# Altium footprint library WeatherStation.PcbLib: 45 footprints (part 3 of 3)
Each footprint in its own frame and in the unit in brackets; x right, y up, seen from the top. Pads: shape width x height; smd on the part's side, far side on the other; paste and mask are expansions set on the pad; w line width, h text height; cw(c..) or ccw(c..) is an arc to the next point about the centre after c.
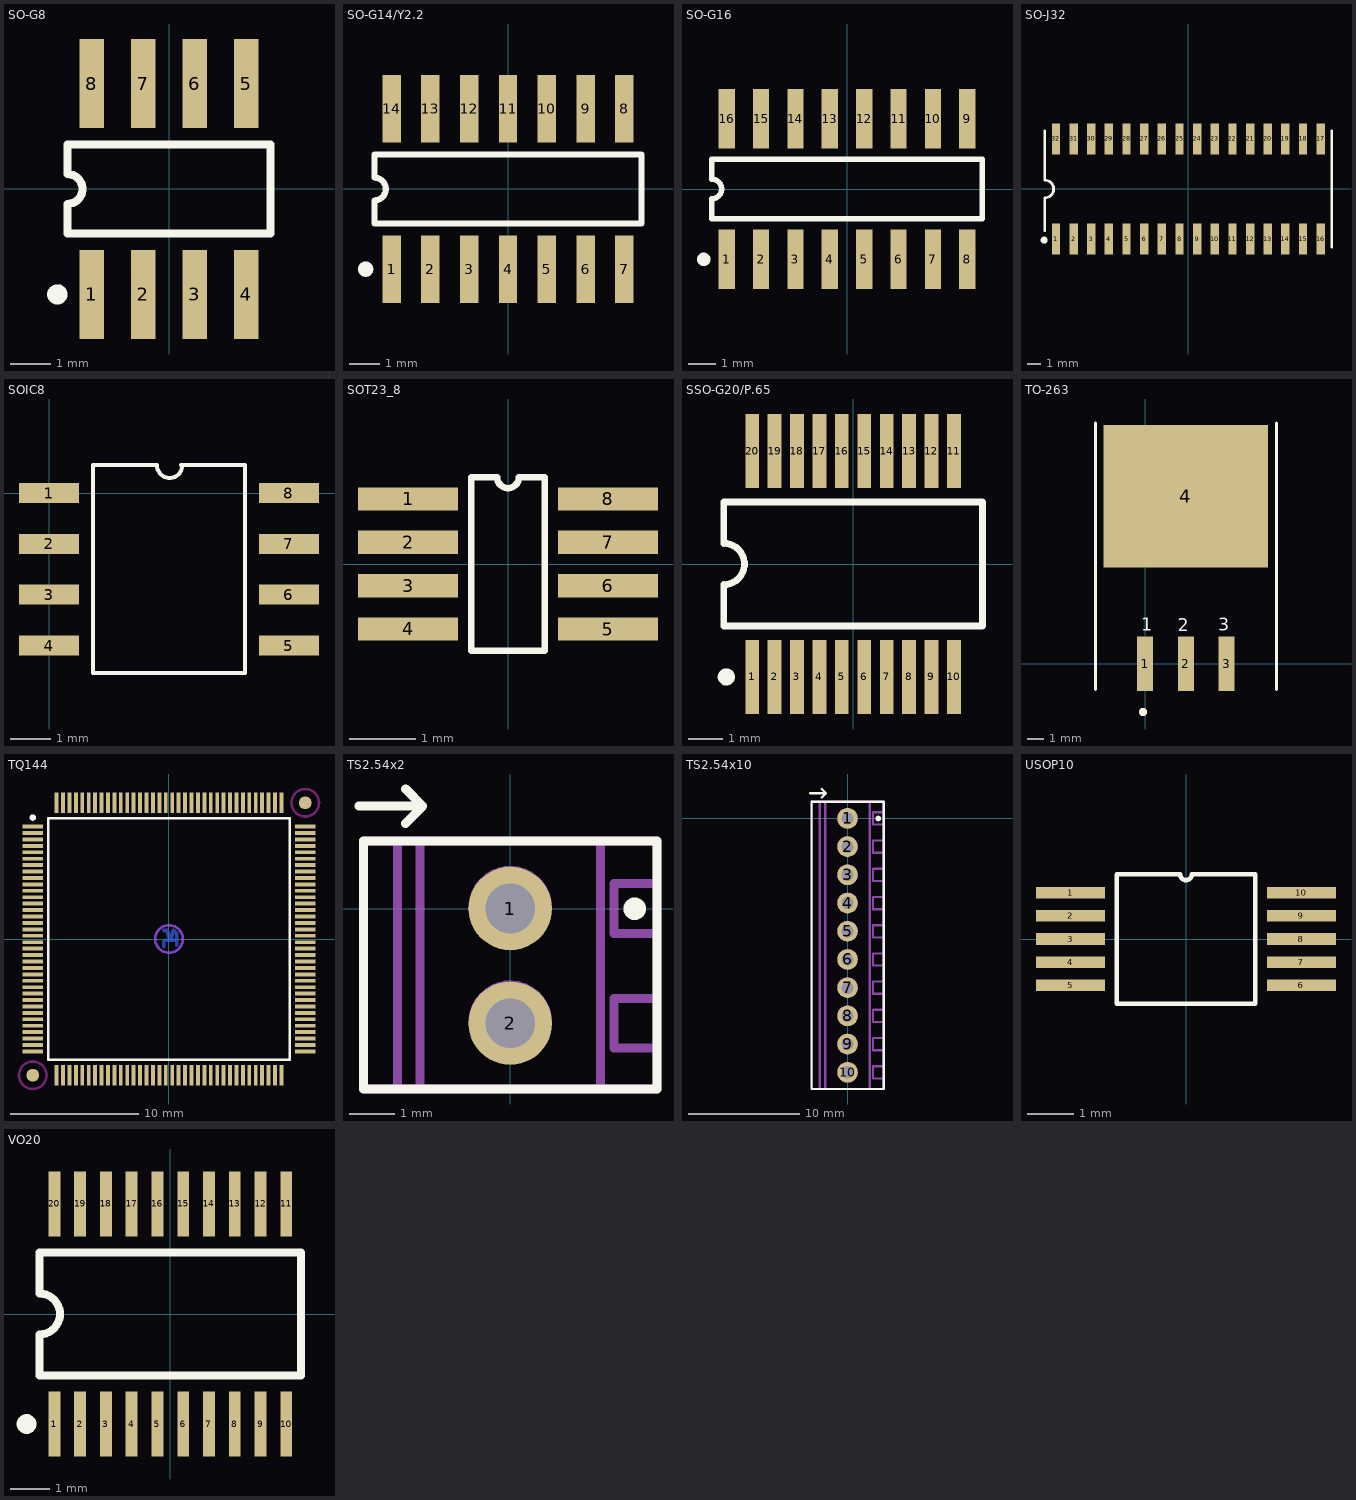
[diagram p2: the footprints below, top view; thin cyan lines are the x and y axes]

## SO-G8 [mm]
pads (8):
  rect 0.6x2.2 smd: 1(-1.905,-2.6) 2(-0.635,-2.6) 3(0.635,-2.6) 4(1.905,-2.6) 5(1.905,2.6) 6(0.635,2.6) 7(-0.635,2.6) 8(-1.905,2.6)
Top Overlay:
  circle w0.25: c-2.755,-2.6 r0.125
  lines w0.2: -2.5,-1.1 -2.5,-0.367 ccw(c-2.5,0) -2.5,0.367 -2.5,1.1 2.5,1.1 2.5,-1.1 -2.5,-1.1

## SO-G14/Y2.2 [mm]
pads (14):
  rect 0.6x2.2 smd: 1(-3.81,-2.625) 2(-2.54,-2.625) 3(-1.27,-2.625) 4(0,-2.625) 5(1.27,-2.625) 6(2.54,-2.625) 7(3.81,-2.625) 8(3.81,2.625) 9(2.54,2.625) 10(1.27,2.625) 11(0,2.625) 12(-1.27,2.625) 13(-2.54,2.625) 14(-3.81,2.625)
Top Overlay:
  circle w0.25: c-4.66,-2.625 r0.125
  lines w0.2: -4.375,-1.125 -4.375,-0.375 ccw(c-4.375,0) -4.375,0.375 -4.375,1.125 4.375,1.125 4.375,-1.125 -4.375,-1.125

## SO-G16 [mm]
pads (16):
  rect 0.6x2.2 smd: 1(-4.445,-2.6) 2(-3.175,-2.6) 3(-1.905,-2.6) 4(-0.635,-2.6) 5(0.635,-2.6) 6(1.905,-2.6) 7(3.175,-2.6) 8(4.445,-2.6) 9(4.445,2.6) 10(3.175,2.6) 11(1.905,2.6) 12(0.635,2.6) 13(-0.635,2.6) 14(-1.905,2.6) 15(-3.175,2.6) 16(-4.445,2.6)
Top Overlay:
  circle w0.25: c-5.295,-2.6 r0.125
  lines w0.2: -5,-1.1 -5,-0.367 ccw(c-5,0) -5,0.367 -5,1.1 5,1.1 5,-1.1 -5,-1.1

## SO-J32 [mm]
pads (32):
  rect 0.6x2.2 smd: 1(-9.525,-3.6) 2(-8.255,-3.6) 3(-6.985,-3.6) 4(-5.715,-3.6) 5(-4.445,-3.6) 6(-3.175,-3.6) 7(-1.905,-3.6) 8(-0.635,-3.6) 9(0.635,-3.6) 10(1.905,-3.6) 11(3.175,-3.6) 12(4.445,-3.6) 13(5.715,-3.6) 14(6.985,-3.6) 15(8.255,-3.6) 16(9.525,-3.6) 17(9.525,3.6) 18(8.255,3.6) 19(6.985,3.6) 20(5.715,3.6) 21(4.445,3.6) 22(3.175,3.6) 23(1.905,3.6) 24(0.635,3.6) 25(-0.635,3.6) 26(-1.905,3.6) 27(-3.175,3.6) 28(-4.445,3.6) 29(-5.715,3.6) 30(-6.985,3.6) 31(-8.255,3.6) 32(-9.525,3.6)
Top Overlay:
  circle w0.25: c-10.375,-3.676 r0.125
  lines w0.2: -10.325,-2.996 -10.325,-0.635 ccw(c-10.325,0) -10.325,0.635 -10.325,4.191 ; 10.325,-4.191 10.325,4.191

## SOIC8 [mm]
pads (8):
  rect 1.5x0.5 smd: 1(0,0) 2(0,-1.27) 3(0,-2.54) 4(0,-3.81) 5(6,-3.81) 6(6,-2.54) 7(6,-1.27) 8(6,0)
Top Overlay:
  lines w0.1: 3.3,0.7 4.9,0.7 4.9,-4.5 1.1,-4.5 1.1,0.7 2.7,0.7 ccw(c3.017,0.7) 3.335,0.7

## SOT23_8 [mm]
pads (8):
  rect 1.5x0.35 smd: 1(-1.5,0.975) 2(-1.5,0.325) 3(-1.5,-0.325) 4(-1.5,-0.975) 5(1.5,-0.975) 6(1.5,-0.325) 7(1.5,0.325) 8(1.5,0.975)
Top Overlay:
  lines w0.1: -0.553,-1.3 0.553,-1.3 0.553,1.3 0.162,1.3 cw(c0,1.3) -0.162,1.3 -0.553,1.3 -0.553,-1.3

## SSO-G20/P.65 [mm]
pads (20):
  rect 0.4x2.15 smd: 1(-2.925,-3.275) 2(-2.275,-3.275) 3(-1.625,-3.275) 4(-0.975,-3.275) 5(-0.325,-3.275) 6(0.325,-3.275) 7(0.975,-3.275) 8(1.625,-3.275) 9(2.275,-3.275) 10(2.925,-3.275) 11(2.925,3.275) 12(2.275,3.275) 13(1.625,3.275) 14(0.975,3.275) 15(0.325,3.275) 16(-0.325,3.275) 17(-0.975,3.275) 18(-1.625,3.275) 19(-2.275,3.275) 20(-2.925,3.275)
Top Overlay:
  circle w0.25: c-3.675,-3.275 r0.125
  lines w0.2: -3.75,-1.8 -3.75,-0.6 ccw(c-3.75,0) -3.75,0.6 -3.75,1.8 3.75,1.8 3.75,-1.8 -3.75,-1.8

## TO-263 [mm]
pads (4):
  rect 1x3.4 smd: 1(0,0) 2(2.54,0) 3(5.08,0)
  rect 10.25x8.9 smd: 4(2.54,10.45)
Top Overlay:
  circle w0.25: c-0.125,-3 r0.125
  lines w0.2: -3.1,-1.6 -3.1,15 ; 8.2,-1.6 8.2,15
  text "1" at -0.25,2.075 h0.8
  text "3" at 4.572,2.075 h0.8
  text "2" at 2.032,2.032 h0.8

## TQ144 [mm]
pads (146):
  rect 1.6x0.3 smd: 1(-10.6,8.75) 2(-10.6,8.25) 3(-10.6,7.75) 4(-10.6,7.25) 5(-10.6,6.75) 6(-10.6,6.25) 7(-10.6,5.75) 8(-10.6,5.25) 9(-10.6,4.75) 10(-10.6,4.25) 11(-10.6,3.75) 12(-10.6,3.25) 13(-10.6,2.75) 14(-10.6,2.25) 15(-10.6,1.75) 16(-10.6,1.25) 17(-10.6,0.75) 18(-10.6,0.25) 19(-10.6,-0.25) 20(-10.6,-0.75) 21(-10.6,-1.25) 22(-10.6,-1.75) 23(-10.6,-2.25) 24(-10.6,-2.75) 25(-10.6,-3.25) 26(-10.6,-3.75) 27(-10.6,-4.25) 28(-10.6,-4.75) 29(-10.6,-5.25) 30(-10.6,-5.75) 31(-10.6,-6.25) 32(-10.6,-6.75) 33(-10.6,-7.25) 34(-10.6,-7.75) 35(-10.6,-8.25) 36(-10.6,-8.75) 73(10.6,-8.75) 74(10.6,-8.25) 75(10.6,-7.75) 76(10.6,-7.25) 77(10.6,-6.75) 78(10.6,-6.25) 79(10.6,-5.75) 80(10.6,-5.25) 81(10.6,-4.75) 82(10.6,-4.25) 83(10.6,-3.75) 84(10.6,-3.25) 85(10.6,-2.75) 86(10.6,-2.25) 87(10.6,-1.75) 88(10.6,-1.25) 89(10.6,-0.75) 90(10.6,-0.25) 91(10.6,0.25) 92(10.6,0.75) 93(10.6,1.25) 94(10.6,1.75) 95(10.6,2.25) 96(10.6,2.75) 97(10.6,3.25) 98(10.6,3.75) 99(10.6,4.25) 100(10.6,4.75) 101(10.6,5.25) 102(10.6,5.75) 103(10.6,6.25) 104(10.6,6.75) 105(10.6,7.25) 106(10.6,7.75) 107(10.6,8.25) 108(10.6,8.75)
  rect 0.3x1.6 smd: 37(-8.75,-10.6) 38(-8.25,-10.6) 39(-7.75,-10.6) 40(-7.25,-10.6) 41(-6.75,-10.6) 42(-6.25,-10.6) 43(-5.75,-10.6) 44(-5.25,-10.6) 45(-4.75,-10.6) 46(-4.25,-10.6) 47(-3.75,-10.6) 48(-3.25,-10.6) 49(-2.75,-10.6) 50(-2.25,-10.6) 51(-1.75,-10.6) 52(-1.25,-10.6) 53(-0.75,-10.6) 54(-0.25,-10.6) 55(0.25,-10.6) 56(0.75,-10.6) 57(1.25,-10.6) 58(1.75,-10.6) 59(2.25,-10.6) 60(2.75,-10.6) 61(3.25,-10.6) 62(3.75,-10.6) 63(4.25,-10.6) 64(4.75,-10.6) 65(5.25,-10.6) 66(5.75,-10.6) 67(6.25,-10.6) 68(6.75,-10.6) 69(7.25,-10.6) 70(7.75,-10.6) 71(8.25,-10.6) 72(8.75,-10.6) 109(8.75,10.6) 110(8.25,10.6) 111(7.75,10.6) 112(7.25,10.6) 113(6.75,10.6) 114(6.25,10.6) 115(5.75,10.6) 116(5.25,10.6) 117(4.75,10.6) 118(4.25,10.6) 119(3.75,10.6) 120(3.25,10.6) 121(2.75,10.6) 122(2.25,10.6) 123(1.75,10.6) 124(1.25,10.6) 125(0.75,10.6) 126(0.25,10.6) 127(-0.25,10.6) 128(-0.75,10.6) 129(-1.25,10.6) 130(-1.75,10.6) 131(-2.25,10.6) 132(-2.75,10.6) 133(-3.25,10.6) 134(-3.75,10.6) 135(-4.25,10.6) 136(-4.75,10.6) 137(-5.25,10.6) 138(-5.75,10.6) 139(-6.25,10.6) 140(-6.75,10.6) 141(-7.25,10.6) 142(-7.75,10.6) 143(-8.25,10.6) 144(-8.75,10.6)
  round 1 smd: FID1(-10.6,-10.6) "FID 2"(10.6,10.6)
Top Layer keep-out:
  circle w0.2: c10.6,10.6 r1.072
  circle w0.2: c-10.6,-10.6 r1.072
Bottom Layer:
  lines w0.3: -0.408,-0.608 -0.408,-0.227 -0.281,-0.1 0.608,-0.1 ; -0.408,0.662 -0.154,0.662 0.075,-0.1 0.354,0.662 0.608,0.408 0.608,-0.481
Bottom Layer keep-out:
  circle w0.2: c0,0 r1.072
Top Overlay:
  circle w0.25: c-10.6,9.45 r0.125
  lines w0.2: -9.4,-9.4 9.4,-9.4 9.4,9.4 -9.4,9.4 -9.4,-9.4

## TS2.54x2 [mm]
pads (2):
  round 1.85 hole 1.1: 1(0,0) 2(0,-2.54)
Top Overlay:
  circle w0.25: c2.76,-0.005 r0.125
  lines w0.2: -3.35,2.27 -1.94,2.27 ; -2.32,1.89 -1.94,2.27 ; -2.32,2.65 -1.94,2.27 ; -3.25,-4 3.25,-4 3.25,1.5 -3.25,1.5 -3.25,-4
Mechanical 15:
  circle w0.254: c0,0.02 r0.8
  circle w0.254: c0,-2.52 r0.8
  lines w0.2: -2.5,1.5 -2.5,-4 ; -2,-4 -2,1.5 ; -0.7,-2.1 0.4,-3.2 ; -0.7,0.4 0.3,-0.6 ; -0.2,-1.84 0.7,-2.74 ; -0.2,0.7 0.7,-0.2 ; 2,-4 2,1.5 ; 3.2,-3.09 2.3,-3.09 2.3,-1.99 3.2,-1.99 ; 3.2,-0.55 2.3,-0.55 2.3,0.55 3.2,0.55 ; -3.25,1.5 3.25,1.5 ; -3.25,1.5 -3.25,-4 -2.5,-4 ; -3.25,1.5 3.25,1.5 ; -2.5,-4 3.25,-4 3.25,1.5

## TS2.54x10 [mm]
pads (10):
  round 1.85 hole 1.1: 1(0,0) 2(0,-2.54) 3(0,-5.08) 4(0,-7.62) 5(0,-10.16) 6(0,-12.7) 7(0,-15.24) 8(0,-17.78) 9(0,-20.32) 10(0,-22.86)
Top Overlay:
  circle w0.25: c2.76,-0.005 r0.125
  lines w0.2: -3.35,2.27 -1.94,2.27 ; -2.32,1.89 -1.94,2.27 ; -2.32,2.65 -1.94,2.27 ; -3.25,-24.36 -3.25,1.5 3.25,1.5 3.25,-24.36 -3.25,-24.36
Mechanical 15:
  circle w0.254: c0,-22.84 r0.8
  circle w0.254: c0,-20.3 r0.8
  circle w0.254: c0,-17.76 r0.8
  circle w0.254: c0,-15.22 r0.8
  circle w0.254: c0,-12.68 r0.8
  circle w0.254: c0,-10.14 r0.8
  circle w0.254: c0,-7.6 r0.8
  circle w0.254: c0,-5.06 r0.8
  circle w0.254: c0,-2.52 r0.8
  circle w0.254: c0,0.02 r0.8
  lines w0.2: -2.5,1.44 -2.5,-24.36 ; -2,-24.3 -2,1.5 ; -0.7,-2.1 0.4,-3.2 ; -0.7,0.4 0.3,-0.6 ; -0.62,-22.43 0.4,-23.44 ; -0.62,-19.93 0.37,-20.92 ; -0.62,-17.39 0.37,-18.38 ; -0.62,-14.84 0.38,-15.84 ; -0.62,-12.32 0.33,-13.27 ; -0.6,-7.2 0.4,-8.2 ; -0.6,-4.7 0.3,-5.6 ; -0.59,-9.79 0.39,-10.77 ; -0.2,-22.16 0.7,-23.06 ; -0.2,-19.62 0.7,-20.52 ; -0.2,-17.08 0.7,-17.98 ; -0.2,-14.54 0.7,-15.44 ; -0.2,-12 0.7,-12.9 ; -0.2,-9.46 0.7,-10.36 ; -0.2,-6.92 0.7,-7.82 ; -0.2,-4.38 0.7,-5.28 ; -0.2,-1.84 0.7,-2.74 ; -0.2,0.7 0.7,-0.2 ; 2,-24.36 2,1.51 ; 3.2,-23.41 2.3,-23.41 2.3,-22.31 3.2,-22.31 ; 3.2,-20.87 2.3,-20.87 2.3,-19.77 3.2,-19.77 ; 3.2,-18.33 2.3,-18.33 2.3,-17.23 3.2,-17.23 ; 3.2,-15.79 2.3,-15.79 2.3,-14.69 3.2,-14.69 ; 3.2,-13.25 2.3,-13.25 2.3,-12.15 3.2,-12.15 ; 3.2,-5.63 2.3,-5.63 2.3,-4.53 3.2,-4.53 ; 3.2,-3.09 2.3,-3.09 2.3,-1.99 3.2,-1.99 ; 3.2,-0.55 2.3,-0.55 2.3,0.55 3.2,0.55 ; -3.2,1.51 3.24,1.51 ; -3.2,1.51 -3.19,-24.35 -2.5,-24.36 ; -3.2,1.51 3.24,1.51 ; -2.5,-24.36 3.24,-24.35 3.24,1.51 ; 2.3,-10.71 3.2,-10.71 2.3,-10.71 ; 2.3,-10.71 2.3,-9.61 ; 2.3,-10.71 2.3,-9.61 ; 2.3,-9.61 3.2,-9.61 2.3,-9.61 ; 2.3,-8.17 3.2,-8.17 2.3,-8.17 ; 2.3,-8.17 2.3,-7.07 ; 2.3,-8.17 2.3,-7.07 ; 2.3,-7.07 3.2,-7.07 2.3,-7.07

## USOP10 [mm]
pads (10):
  rect 1.5x0.25 smd: 1(-2.5,1) 2(-2.5,0.5) 3(-2.5,0) 4(-2.5,-0.5) 5(-2.5,-1) 6(2.5,-1) 7(2.5,-0.5) 8(2.5,0) 9(2.5,0.5) 10(2.5,1)
Top Overlay:
  lines w0.1: -0.15,1.4 -1.5,1.4 -1.5,-1.4 1.5,-1.4 1.5,1.4 0.15,1.4 ; -0.125,1.4 ccw(c0,1.4) 0.125,1.4

## VO20 [mm]
pads (20):
  rect 0.3x1.65 smd: 1(-2.925,-2.775) 2(-2.275,-2.775) 3(-1.625,-2.775) 4(-0.975,-2.775) 5(-0.325,-2.775) 6(0.325,-2.775) 7(0.975,-2.775) 8(1.625,-2.775) 9(2.275,-2.775) 10(2.925,-2.775) 11(2.925,2.775) 12(2.275,2.775) 13(1.625,2.775) 14(0.975,2.775) 15(0.325,2.775) 16(-0.325,2.775) 17(-0.975,2.775) 18(-1.625,2.775) 19(-2.275,2.775) 20(-2.925,2.775)
Top Overlay:
  circle w0.25: c-3.625,-2.775 r0.125
  lines w0.2: -3.3,-1.55 -3.3,-0.517 ccw(c-3.3,0) -3.3,0.517 -3.3,1.55 3.3,1.55 3.3,-1.55 -3.3,-1.55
